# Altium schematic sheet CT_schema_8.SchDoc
size 251 x 159 mm
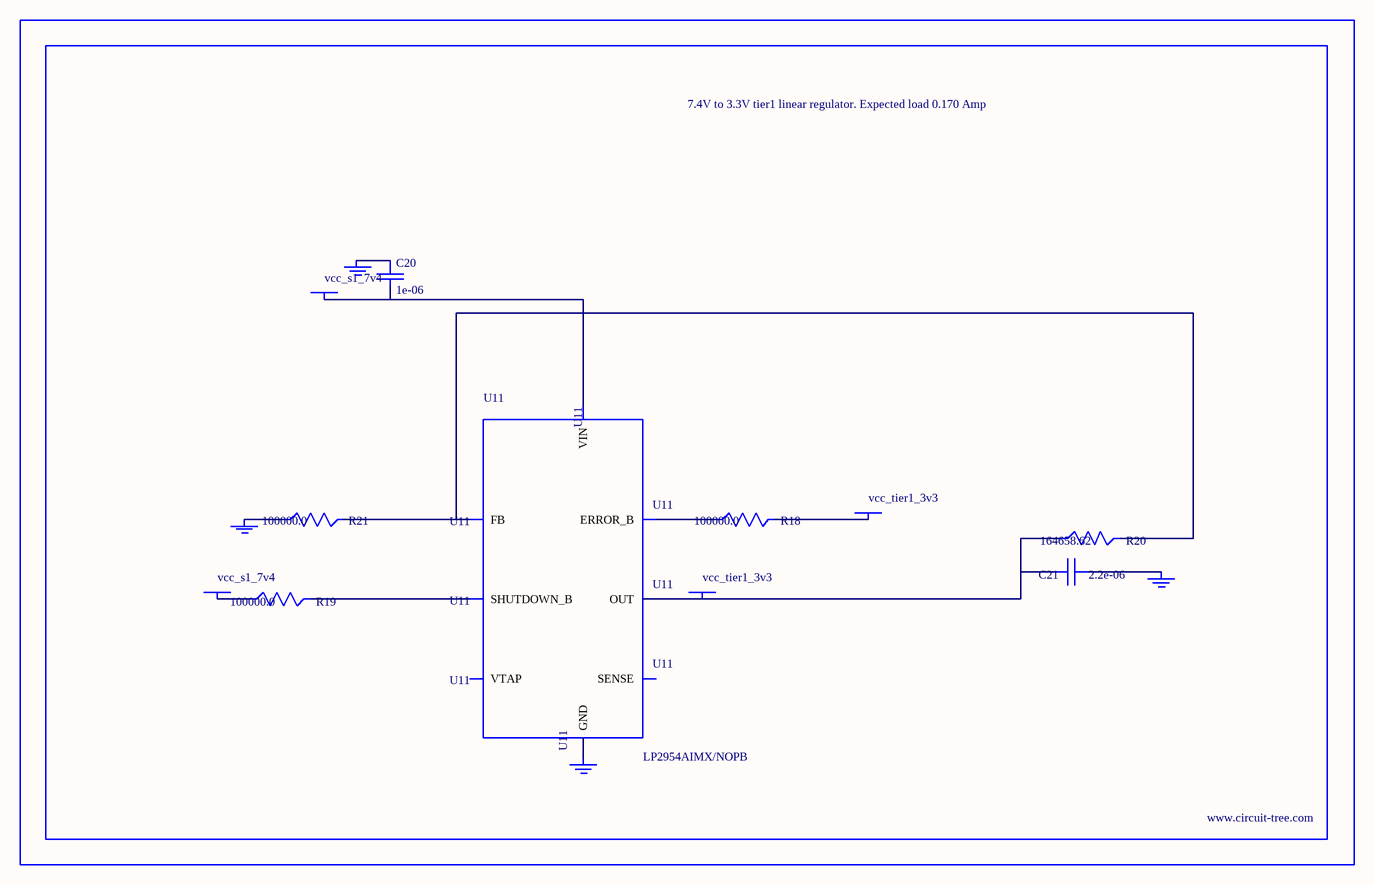
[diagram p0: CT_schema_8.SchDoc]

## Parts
BORDER7  (no value)
C20  1e-06  [EXV-9B]
C21  2.2e-06  [EXV-9B]
GND_INSTANCE_7_0  (no value)
GND_INSTANCE_7_1  (no value)
GND_INSTANCE_7_2  (no value)
GND_INSTANCE_7_3  (no value)
POWER_INSTANCE_7_0  vcc_s1_7v4
POWER_INSTANCE_7_1  vcc_tier1_3v3
POWER_INSTANCE_7_2  vcc_s1_7v4
POWER_INSTANCE_7_3  vcc_tier1_3v3
R18  100000.0  [R0603]
R19  100000.0  [R0603]
R20  164658.62  [R0603]
R21  100000.0  [R0603]
U11  LP2954AIMX/NOPB  [LP2954]

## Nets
NetC20_1: C20.1 GND_INSTANCE_7_2.0(GND)
NetC20_2: C20.2 POWER_INSTANCE_7_2.0(PWR) U11.8(VIN)
NetC21_1: C21.1 GND_INSTANCE_7_0.0(GND)
NetC21_2: C21.2 POWER_INSTANCE_7_3.0(PWR) R20.1 U11.1(OUT)
NetGND_INSTANCE_7_1_0: GND_INSTANCE_7_1.0(GND) R21.1
NetGND_INSTANCE_7_3_0: GND_INSTANCE_7_3.0(GND) U11.4(GND)
NetPOWER_INSTANCE_7_0_0: POWER_INSTANCE_7_0.0(PWR) R19.1
NetPOWER_INSTANCE_7_1_0: POWER_INSTANCE_7_1.0(PWR) R18.2
NetR18_1: R18.1 U11.5(ERROR_B)
NetR19_2: R19.2 U11.3(SHUTDOWN_B)
NetR20_2: R20.2 R21.2 U11.7(FB)

Not connected (* = marked no-connect by the designer): U11 2(SENSE) 6(VTAP)

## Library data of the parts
BORDER7 = BORDER_PAGE7
C20 = EDK105M050A9BAA
C21 = EDK225M050A9BAA
GND_INSTANCE_7_0-GND_INSTANCE_7_3 = GND
POWER_INSTANCE_7_0-POWER_INSTANCE_7_3 = PWR
R18 R19 R21 = RC0603JR-07100KL
R20 = R20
